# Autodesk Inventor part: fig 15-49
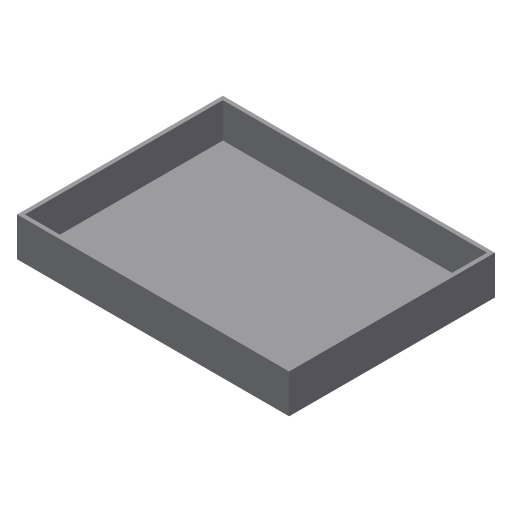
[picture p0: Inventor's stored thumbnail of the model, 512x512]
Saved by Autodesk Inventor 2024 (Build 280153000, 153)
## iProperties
Shininess: 77.0
Angle Display Precision: 2
Document Length Units: 11269
Document Angle Units: 11279
Document Time Units: 11290
Document Mass Units: 11283
Document Length Units Precision: 3
Document Angle Units Precision: 2
Compacted: True
Created: 2002-04
Part Number: fig 15-49
Document SubType Name: Sheet Metal
Density: 1 g/cm^3
Sheet Metal Rule: Default
Material: Generic
Appearance: Default
Density: 0.0
Volumn: 0.0
Area: 0.0
PropertySet Name: Model Information
Control State: 0
Master: False
Checked Out: False
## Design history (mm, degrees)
sketch "Sketch1"
  geometry: L1 (-34, 28)-(36, 28); L2 (36, 28)-(36, -24.941); L3 (36, -24.941)-(-34, -24.941); L4 (-34, -24.941)-(-34, 28)
  constraints: 8 end point, 2 parallel, 1 horizontal, 1 perpendicular
extrude "Extrusion1" new body sketch "Sketch1" distance "d0" = 10; taper "d1" = 0 deg
shell "Shell1" dims "d2" = 1
body "Solid1"
other parameters: "Thickness" = 1, "BendRadius" = 1 (= Thickness), "BendReliefWidth" = 1 (= Thickness), "BendReliefDepth" = 0.5 (= 0.5 x Thickness), "CornerReliefSize" = 4 (= 4 x Thickness), "SeamGap" = 0.01, "MinimumRemnant" = 2 (= 2 x Thickness), "TransitionRadius" = 1 (= BendRadius), "JacobiRadiusSize" = 1 (= Thickness), "GapSize" = 1 (= Thickness)
